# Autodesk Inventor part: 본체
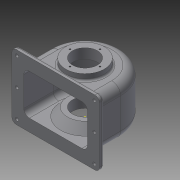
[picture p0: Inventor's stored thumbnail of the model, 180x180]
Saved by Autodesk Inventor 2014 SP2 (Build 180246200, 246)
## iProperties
Created: 2015-09
Part Number: 본체
Material: 일반
Document SubType Name: Modeling
Designer: 201-01
Density: 1 g/cm^3
Appearance: 기본값
Author: 201-01
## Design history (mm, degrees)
sketch "스케치1"
  geometry: L1 (-79.8, 0)-(79.8, 0) reference; L2 (0, -67.8)-(0, 77.8) reference; L3 (57, 0)-(57, -47); L4 (57, -47)-(-57, -47); L5 (-57, -47)-(-57, 0); A1 r 57 centre (0, 0) between (57, 0) and (-57, 0); 1 further point
  constraints: 6 end point, 2 coincident, 2 parallel, 2 point on circle, 2 tangent, 1 centre point, 1 perpendicular
  dimensions: "d1" = 47 distance of L3.start L3.end; "d2" = 57 radius of A1
extrude "돌출1" new body sketch "스케치1" distance "d3" = 77; taper "d4" = 0 deg
feature "쉘1" dims "d5" = 6
sketch "스케치2"
  geometry: C1 r 31 at (0, 0); 1 further point
  constraints: 1 centre point, 1 coincident
  dimensions: "d6" = 62 diameter of C1
extrude "돌출2" join sketch "스케치2" distance "d7" = 10; taper "d8" = 0 deg
hole "구멍1" diameter "d11" = 40; stored, may be unused: countersink angle "d15" = 90 deg, drill point angle "d17" = 0 deg; dims "d9" = 10, "d10" = 10, "d12" = 6, "d13" = 4, "d14" = 2, "d16" = 20
sketch "스케치3"
  geometry: C1 r 28 at (0, 0); 1 further point
  constraints: 1 centre point, 1 coincident
  dimensions: "d18" = 56 diameter of C1
extrude "돌출3" join sketch "스케치3" distance "d19" = 19; taper "d20" = 0 deg
feature "면 기울기2" dims angle "d47" = 40 deg
hole "구멍2" diameter "d50" = 40; stored, may be unused: countersink angle "d54" = 90 deg, drill point angle "d56" = 0 deg; dims "d48" = 10, "d49" = 10, "d51" = 6, "d52" = 4, "d53" = 2, "d55" = 20
hole "구멍3" diameter "d59" = 66; stored, may be unused: countersink angle "d63" = 90 deg, drill point angle "d65" = 0 deg; dims "d60" = 6, "d61" = 4, "d62" = 2, "d64" = 5, "d66" = 10, "d67" = 10
feature "면 기울기3" dims angle "d68" = 40 deg
sketch "스케치7"
  geometry: C1 r 33 at (0, 0) reference; 1 further point
extrude "돌출4" join sketch "스케치7" distance "d69" = 2; taper "d70" = 0 deg
sketch "스케치8"
  geometry: 1 further point
sketch "스케치9"
  geometry: C1 r 20 at (0, 0); 1 further point
  constraints: 2 coincident, 1 centre point
  dimensions: "d71" = 40 diameter of C1
extrude "돌출5" cut sketch "스케치9" distance "d72" = 4; taper "d73" = 0 deg
sketch "스케치11"
  geometry: L1 (-13, -13.5)-(127, -13.5); L2 (127, -13.5)-(127, 90.5); L3 (127, 90.5)-(-13, 90.5); L4 (-13, 90.5)-(-13, -13.5); L5 (0, 0)-(0, 77) reference; L6 (114, 0)-(114, 77) reference; L7 (57, -34.3)-(57, 111.3) reference; L8 (114, 0)-(0, 0) reference; L9 (0, 77)-(114, 77) reference; 3 further points
  constraints: 8 end point, 2 midpoint, 2 parallel, 1 horizontal, 1 perpendicular, 1 vertical alignment
  dimensions: "d75" = 104 distance of L3.end L1.start; "d76" = 140 distance of L1.start L1.end; "d77" = 13.5 distance between parallel lines of L1 L8
extrude "돌출6" join sketch "스케치11" distance "d78" = 7; taper "d79" = 0 deg
node "작업 평면2"
sketch "스케치12"
  geometry: L1 (70, 90.5)-(-70, 90.5) reference; L2 (-70, 90.5)-(-70, -13.5) reference; L3 (-70, -13.5)-(70, -13.5) reference; L4 (70, -13.5)-(70, 90.5) reference; C1 r 6 at (0, 38.5); 1 further point
  constraints: 1 centre point
  dimensions: "d82" = 12 diameter of C1; "d83" = 70 distance from line of L2 C1.centre; "d84" = 52 distance from line of L1 C1.centre
extrude "돌출7" join sketch "스케치12" stored distance "d85" = 7; taper "d86" = 0 deg
feature "면 기울기4" dims angle "d87" = 10 deg
fillet "모깎기1" dims "d88" = 14
fillet "모깎기2" dims "d89" = 7
fillet "모깎기3" dims "d90" = 1
fillet "모깎기4" dims "d91" = 3
fillet "모깎기5" dims "d92" = 3
hole "구멍4" diameter "d95" = 4.134; stored, may be unused: countersink angle "d99" = 90 deg, drill point angle "d101" = 118 deg; dims "d96" = 20, "d97" = 4, "d98" = 2, "d100" = 3, "d146" = 10, "d147" = 10
sketch "스케치13" dims "d102" = 56
  geometry: 3 further points
  constraints: 2 coincident, 1 vertical alignment, 2 other
hole "구멍5" sketch "스케치13" at (0, 28) diameter "d103" = 2.459; stored, may be unused: countersink angle "d107" = 90 deg, drill point angle "d109" = 118 deg; dims "d104" = 7, "d105" = 4, "d106" = 2, "d108" = 9
sketch "스케치14" dims "d113" = 48
  geometry: 3 further points
  constraints: 1 coincident, 1 vertical alignment, 2 other
hole "구멍6" sketch "스케치14" at (0, 24) diameter "d114" = 2.459; stored, may be unused: countersink angle "d118" = 90 deg, drill point angle "d120" = 118 deg; dims "d115" = 6, "d116" = 4, "d117" = 2, "d119" = 8
sketch "스케치15"
  geometry: L1 (-13, 6.5)-(-13, -83.5) reference; L2 (120, 13.5)-(-6, 13.5) reference; L3 (57, 34.3)-(57, -111.3) reference; L4 (57, -38.5)-(-20.152, -38.5); C1 r 2.5 at (-5, 5.5); C2 r 2.5 at (119, 5.5); C3 r 2.5 at (-5, -82.5); C4 r 2.5 at (119, -82.5); C5 r 2.5 at (-5, -38.5); C6 r 2.5 at (119, -38.5); 1 further point
  constraints: 6 centre point, 4 symmetric about line, 2 end point, 1 midpoint, 1 perpendicular, 4 other
  dimensions: "d124" = 5 diameter of C1; "d125" = 8 distance from line of L1 C1.centre; "d126" = 8 distance from line of C1.centre L2; "d138" = 5 diameter of C5; "d139" = 0 vertical distance of L4.end C5.centre; "d140" = 8 distance from line of L1 C5.centre
sketch "스케치16"
  geometry: L1 (69.5, -47)-(-20.5, -47) reference; L2 (-14, 0)-(-14, -39) reference; 1 further point
  constraints: 1 other
  dimensions: "d134" = 30 distance from line of point (24.5, -17) L1; "d135" = 38.5 distance from line of point (24.5, -17) L2
feature "엠보싱1" sketch "스케치16" dims "d18" = 56, "d136" = 0.5, "d137" = 0
extrude "돌출10" cut sketch "스케치15" stored distance "d141" = 7; taper "d142" = 0 deg
fillet "모깎기6" dims "d143" = 9
fillet "모깎기7" dims "d144" = 3
fillet "모깎기8" dims "d145" = 0.5
node "솔리드1"
pattern_circular "원형 패턴1" dims angle "d111" = 360 deg
pattern_circular "원형 패턴2" dims angle "d122" = 360 deg
other parameters: "d0" = 57, "d80" = 63
